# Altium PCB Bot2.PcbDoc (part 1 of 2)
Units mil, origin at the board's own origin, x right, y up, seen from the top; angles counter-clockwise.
Board outline 1717.4 x 2323.5 mil, 2 copper layers (Top1, Bottom2), stack 14.611 mil thick; 246 components, 15 nets, 1108 pads, 443 vias.
Unrouted connection lines stored in the file: 11.
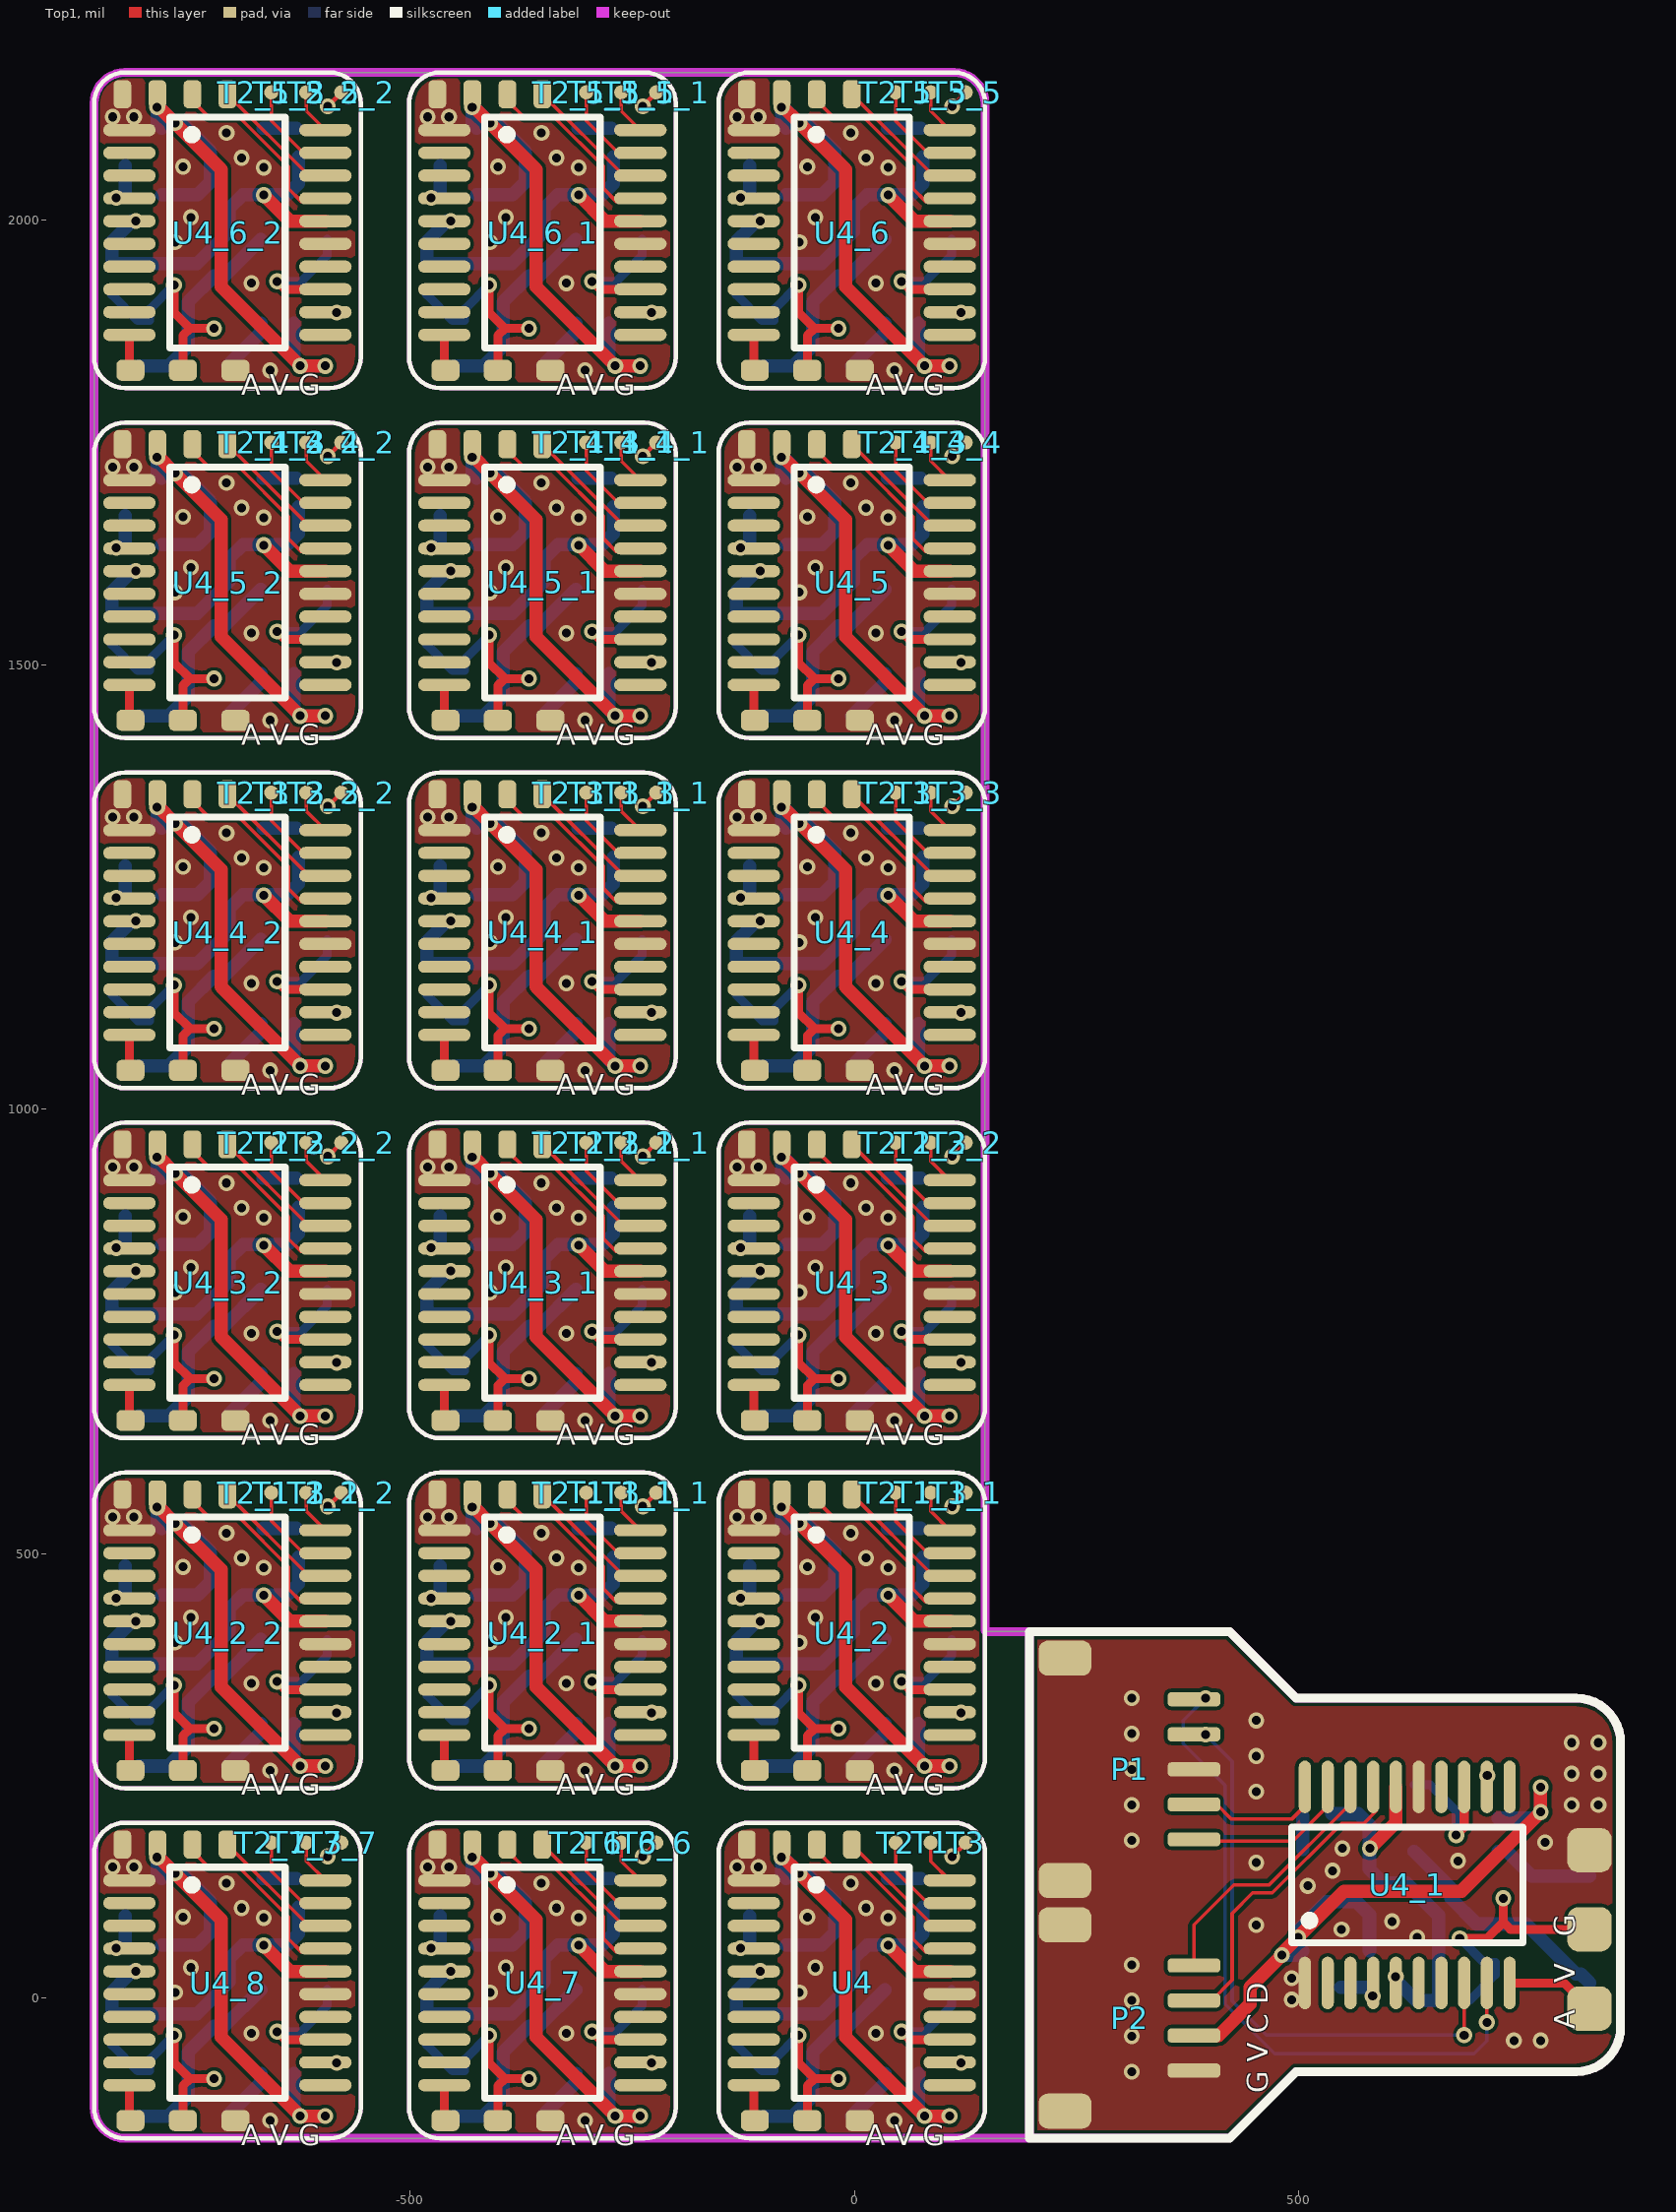
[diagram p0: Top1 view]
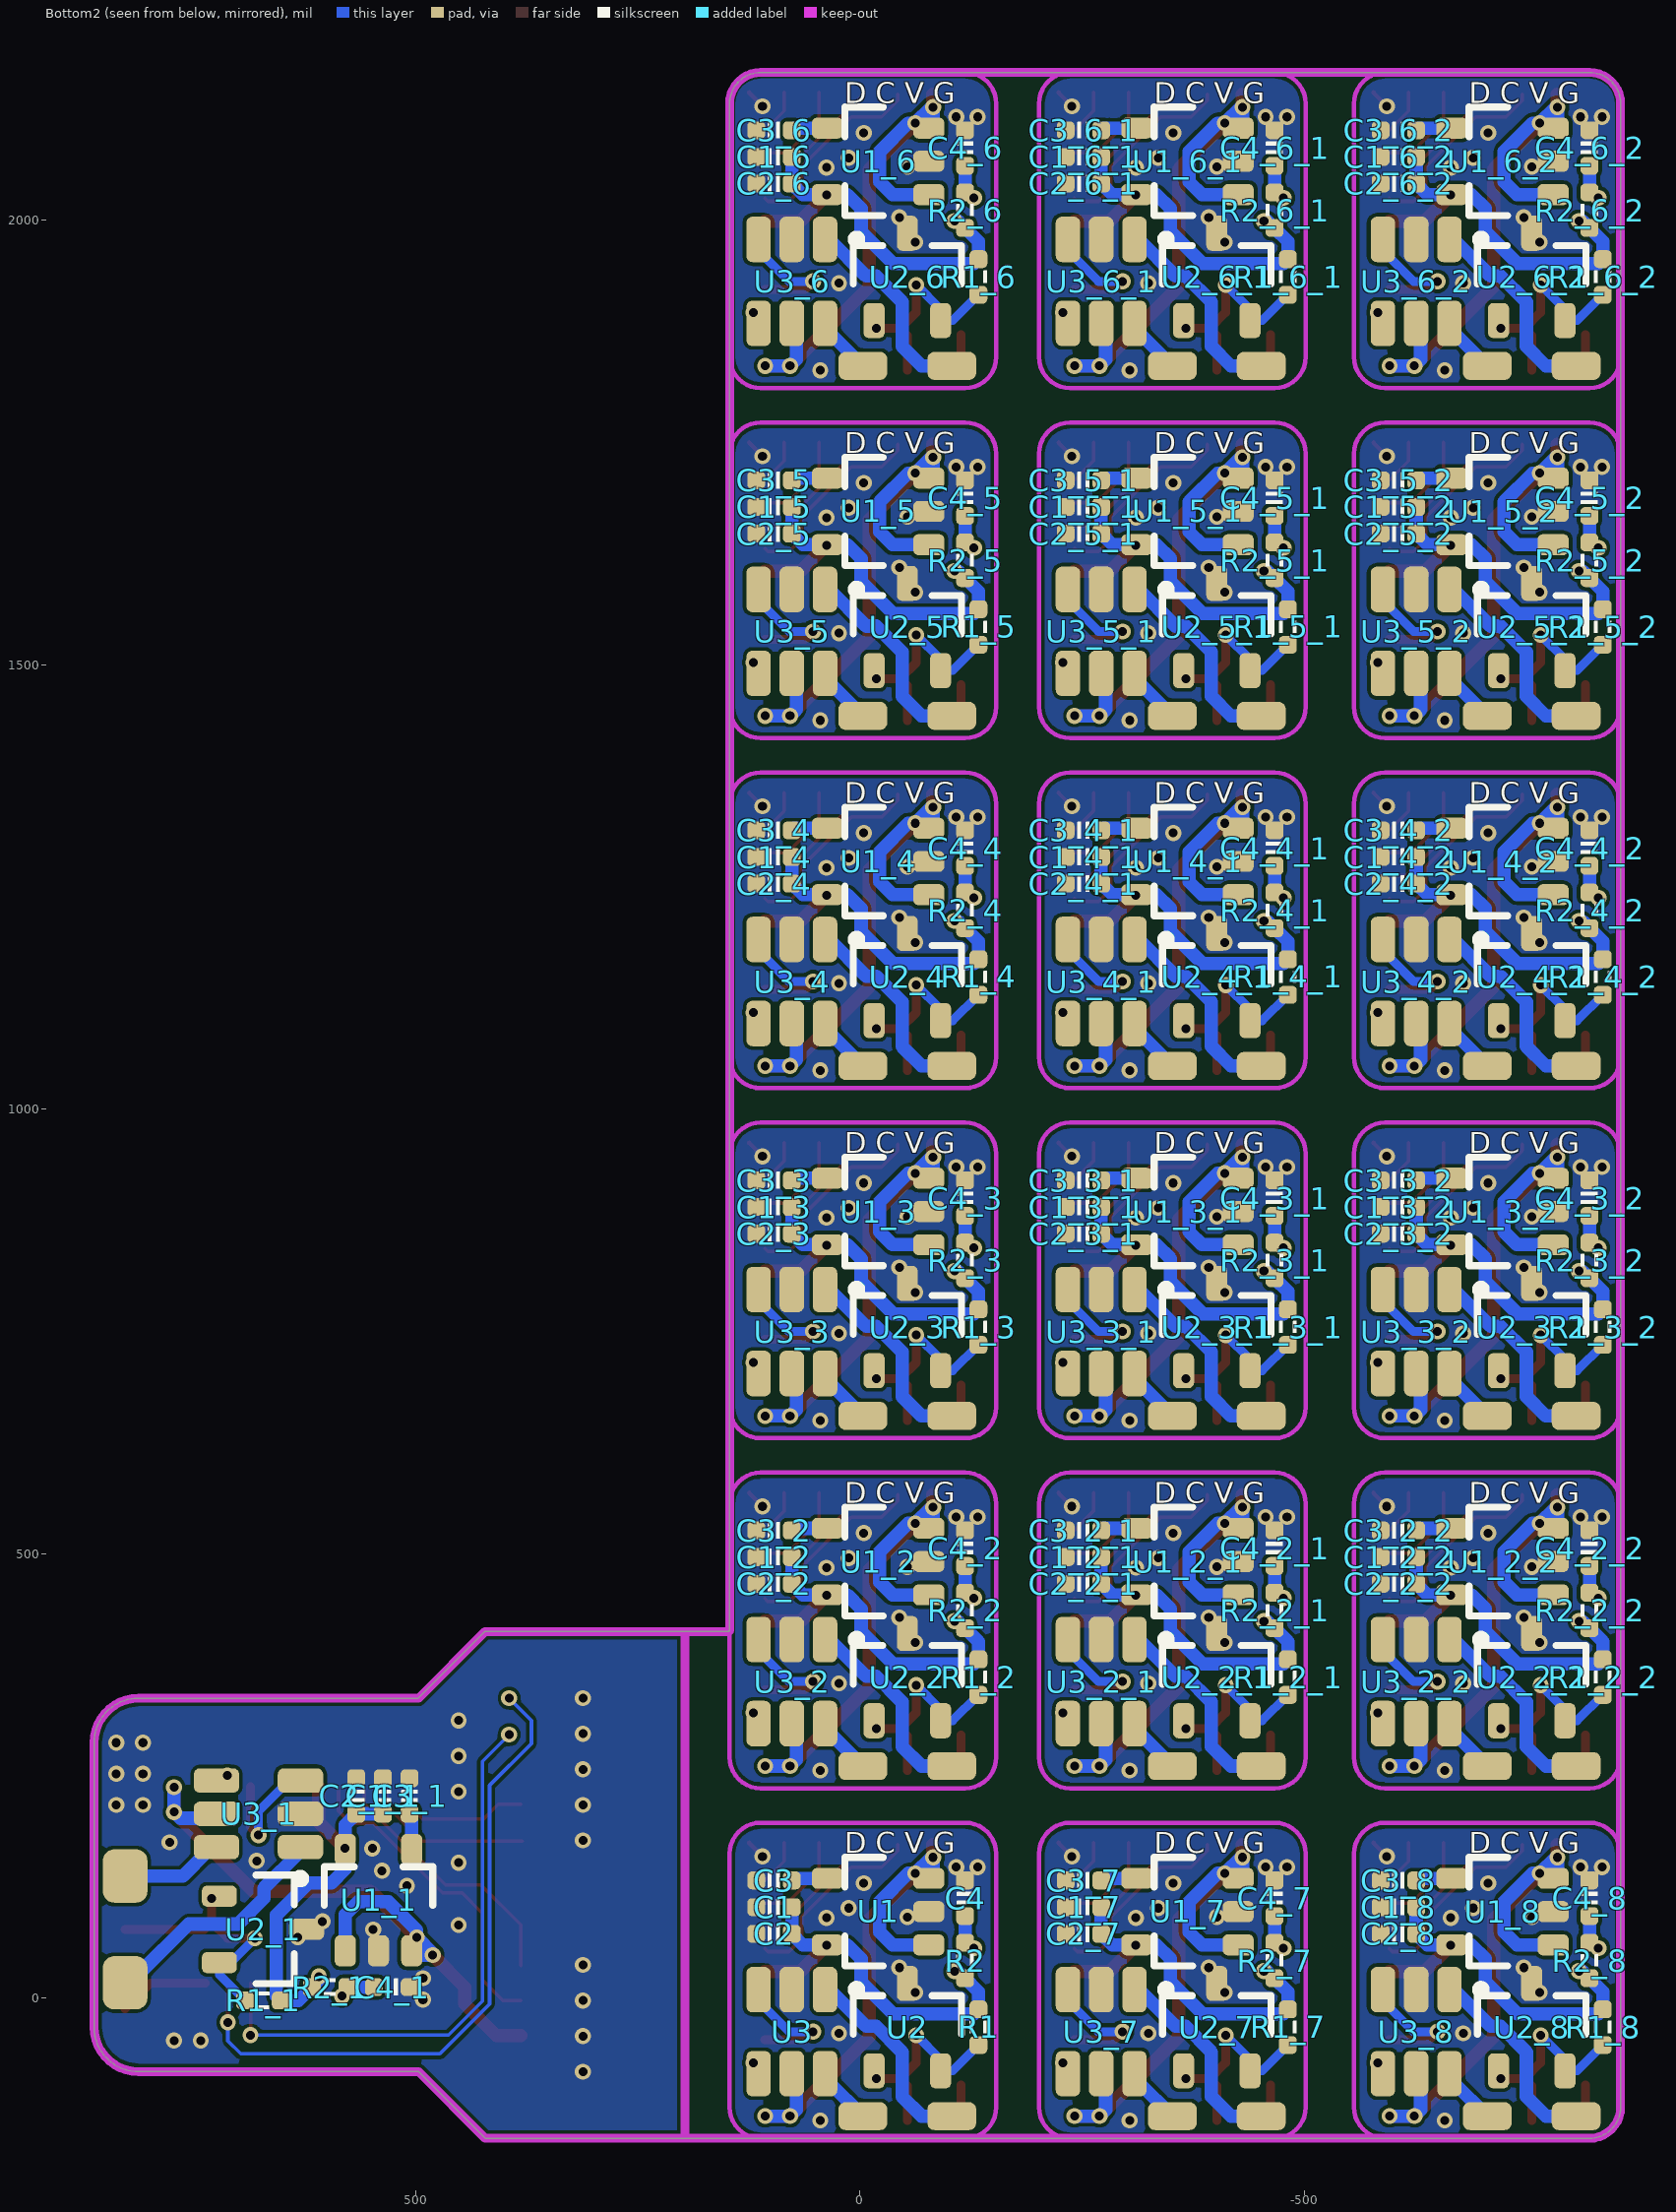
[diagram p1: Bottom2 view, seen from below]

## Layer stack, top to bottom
Top Solder: solder mask 0.4, Solder Resist, Dk 3.5
Top1: signal copper 1.4
Dielectric 1: prepreg 11.811, PP-006, Dk 4.1
Bottom2: signal copper 1.4
Bottom Solder: solder mask 0.4, Solder Resist, Dk 3.5

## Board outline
-855.55,-122.48 ccw(c-820.55,-122.48) -820.55,-157.48 421.85,-157.48 496.85,-82.48 811.85,-82.48 ccw(c811.85,-32.48) 861.85,-32.48 861.85,287.52 ccw(c811.85,287.52) 811.85,337.52 496.85,337.52 421.85,412.52 148.09,412.52 146.89,413.72 146.89,2131.02 ccw(c111.89,2131.02) 111.89,2166.02 -820.55,2166.02 ccw(c-820.55,2131.02) -855.55,2131.02

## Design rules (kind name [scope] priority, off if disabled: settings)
Clearance Clearance_Logo [InNetClass('Logo')] p1: gap=8 ignorepadtopadclearanceinfootprint=FALSE
Clearance [All] p2: gap=4 ignorepadtopadclearanceinfootprint=FALSE except(0: Arc-Hole Track-Hole SMDPad-Hole THPad-Hole Via-Hole Fill-Hole Poly-Hole Region-Hole Text-Hole)
ComponentClearance [All] p1: gap=0 collisioncheckmode=3 verticalgap=0 showdistances=FALSE
DiffPairsRouting [All] p1: maxlimit=9 minlimit=9 mostfreqgap=9 toplayer_minwidth=15 toplayer_maxwidth=15 toplayer_prefwidth=15 bottomlayer_minwidth=15 bottomlayer_maxwidth=15 bottomlayer_prefwidth=15 maxuncoupledlength=500
FanoutControl Fanout_BGA [All] p1: bgadir=Out bgaviamode=Centered fanoutstyle=Auto fanoutdirection=Alternating viagrid=1 // Fanout_BGA (Default Rule)
HoleSize [All] p1: absolutevalues=TRUE maxlimit=10000 minlimit=8 maxpercent=80.000 minpercent=20.000
MinimumSolderMaskSliver [All] p1 off: minsoldermaskwidth=2
PlaneClearance [All] p1: clearance=8
PlaneConnect [All] p1: planeconnectstyle=Direct reliefexpansion=20 reliefentries=4 reliefconductorwidth=10 reliefairgap=10
PolygonConnect [All] p1: connectstyle=Direct reliefconductorwidth=10 reliefentries=4 polygonreliefangle="90 Angle" airgapwidth=10
RoutingVias [All] p1: holewidth=8 width=16 viastyle="Through Hole" minholewidth=6 minwidth=12 maxholewidth=28 maxwidth=50
SilkToSilkClearance [All] p1: silktosilkclearance=0
SilkToSolderMaskClearance [IsPad] p1: minsilkscreentomaskgap=0 clearancetoexposedcopper=TRUE
SolderMaskExpansion [All] p1: expansion=3 istentingtop=FALSE
Width Logo [InNetClass('Logo')] p1: maxlimit=100 minlimit=0.1 preferedwidth=10
Width GND [(InNet('AGND') OR InNet('GND'))] p2: maxlimit=50 minlimit=4 preferedwidth=10
Width VCC [(InNet('VDD_SYS_3.3V') OR InNet('VDD_AV_3.3V') OR InNet('VDD_5V') OR InNet('VDD1V2-SYS') OR InNet('VDD1V1-EPHY') OR InNet('VDD-CPUX') OR InNet('VDD-CPUS') OR InNet('VDD-CPUFB') OR InNet('VCC-DRAM'))] p3: maxlimit=50 minlimit=4 preferedwidth=10
Width [All] p4: maxlimit=10000 minlimit=4 preferedwidth=4
21 further rules are at their usual default settings.

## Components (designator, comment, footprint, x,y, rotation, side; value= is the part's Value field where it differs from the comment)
C1 "10uF" CAP_0402 96.89,102.52 r180 bottom value=0.1u
C1_1 "10uF" CAP_0402 536.85,227.52 r270 bottom value=0.1u (schematic designator C1)
C1_2 "10uF" CAP_0402 96.89,496.22 r180 bottom value=0.1u (schematic designator C1)
C1_2_1 "10uF" CAP_0402 -251.22,496.22 r180 bottom value=0.1u (schematic designator C1)
C1_2_2 "10uF" CAP_0402 -605.55,496.22 r180 bottom value=0.1u (schematic designator C1)
C1_3 "10uF" CAP_0402 96.89,889.92 r180 bottom value=0.1u (schematic designator C1)
C1_3_1 "10uF" CAP_0402 -251.22,889.92 r180 bottom value=0.1u (schematic designator C1)
C1_3_2 "10uF" CAP_0402 -605.55,889.92 r180 bottom value=0.1u (schematic designator C1)
C1_4 "10uF" CAP_0402 96.89,1283.62 r180 bottom value=0.1u (schematic designator C1)
C1_4_1 "10uF" CAP_0402 -251.22,1283.62 r180 bottom value=0.1u (schematic designator C1)
C1_4_2 "10uF" CAP_0402 -605.55,1283.62 r180 bottom value=0.1u (schematic designator C1)
C1_5 "10uF" CAP_0402 96.89,1677.32 r180 bottom value=0.1u (schematic designator C1)
C1_5_1 "10uF" CAP_0402 -251.22,1677.32 r180 bottom value=0.1u (schematic designator C1)
C1_5_2 "10uF" CAP_0402 -605.55,1677.32 r180 bottom value=0.1u (schematic designator C1)
C1_6 "10uF" CAP_0402 96.89,2071.02 r180 bottom value=0.1u (schematic designator C1)
C1_6_1 "10uF" CAP_0402 -251.22,2071.02 r180 bottom value=0.1u (schematic designator C1)
C1_6_2 "10uF" CAP_0402 -605.55,2071.02 r180 bottom value=0.1u (schematic designator C1)
C1_7 "10uF" CAP_0402 -251.22,102.52 r180 bottom value=0.1u (schematic designator C1)
C1_8 "10uF" CAP_0402 -605.55,102.52 r180 bottom value=0.1u (schematic designator C1)
C2 "0.1uF" CAP_0402 96.89,72.52 r180 bottom value=0.1u
C2_1 "0.1uF" CAP_0402 566.85,227.52 r270 bottom value=0.1u (schematic designator C2)
C2_2 "0.1uF" CAP_0402 96.89,466.22 r180 bottom value=0.1u (schematic designator C2)
C2_2_1 "0.1uF" CAP_0402 -251.22,466.22 r180 bottom value=0.1u (schematic designator C2)
C2_2_2 "0.1uF" CAP_0402 -605.55,466.22 r180 bottom value=0.1u (schematic designator C2)
C2_3 "0.1uF" CAP_0402 96.89,859.92 r180 bottom value=0.1u (schematic designator C2)
C2_3_1 "0.1uF" CAP_0402 -251.22,859.92 r180 bottom value=0.1u (schematic designator C2)
C2_3_2 "0.1uF" CAP_0402 -605.55,859.92 r180 bottom value=0.1u (schematic designator C2)
C2_4 "0.1uF" CAP_0402 96.89,1253.62 r180 bottom value=0.1u (schematic designator C2)
C2_4_1 "0.1uF" CAP_0402 -251.22,1253.62 r180 bottom value=0.1u (schematic designator C2)
C2_4_2 "0.1uF" CAP_0402 -605.55,1253.62 r180 bottom value=0.1u (schematic designator C2)
C2_5 "0.1uF" CAP_0402 96.89,1647.32 r180 bottom value=0.1u (schematic designator C2)
C2_5_1 "0.1uF" CAP_0402 -251.22,1647.32 r180 bottom value=0.1u (schematic designator C2)
C2_5_2 "0.1uF" CAP_0402 -605.55,1647.32 r180 bottom value=0.1u (schematic designator C2)
C2_6 "0.1uF" CAP_0402 96.89,2041.02 r180 bottom value=0.1u (schematic designator C2)
C2_6_1 "0.1uF" CAP_0402 -251.22,2041.02 r180 bottom value=0.1u (schematic designator C2)
C2_6_2 "0.1uF" CAP_0402 -605.55,2041.02 r180 bottom value=0.1u (schematic designator C2)
C2_7 "0.1uF" CAP_0402 -251.22,72.52 r180 bottom value=0.1u (schematic designator C2)
C2_8 "0.1uF" CAP_0402 -605.55,72.52 r180 bottom value=0.1u (schematic designator C2)
C3 "10nF" CAP_0402 96.89,132.52 r0 bottom value=0.1u
C3_1 "10nF" CAP_0402 506.85,227.52 r90 bottom value=0.1u (schematic designator C3)
C3_2 "10nF" CAP_0402 96.89,526.22 r0 bottom value=0.1u (schematic designator C3)
C3_2_1 "10nF" CAP_0402 -251.22,526.22 r0 bottom value=0.1u (schematic designator C3)
C3_2_2 "10nF" CAP_0402 -605.55,526.22 r0 bottom value=0.1u (schematic designator C3)
C3_3 "10nF" CAP_0402 96.89,919.92 r0 bottom value=0.1u (schematic designator C3)
C3_3_1 "10nF" CAP_0402 -251.22,919.92 r0 bottom value=0.1u (schematic designator C3)
C3_3_2 "10nF" CAP_0402 -605.55,919.92 r0 bottom value=0.1u (schematic designator C3)
C3_4 "10nF" CAP_0402 96.89,1313.62 r0 bottom value=0.1u (schematic designator C3)
C3_4_1 "10nF" CAP_0402 -251.22,1313.62 r0 bottom value=0.1u (schematic designator C3)
C3_4_2 "10nF" CAP_0402 -605.55,1313.62 r0 bottom value=0.1u (schematic designator C3)
C3_5 "10nF" CAP_0402 96.89,1707.32 r0 bottom value=0.1u (schematic designator C3)
C3_5_1 "10nF" CAP_0402 -251.22,1707.32 r0 bottom value=0.1u (schematic designator C3)
C3_5_2 "10nF" CAP_0402 -605.55,1707.32 r0 bottom value=0.1u (schematic designator C3)
C3_6 "10nF" CAP_0402 96.89,2101.02 r0 bottom value=0.1u (schematic designator C3)
C3_6_1 "10nF" CAP_0402 -251.22,2101.02 r0 bottom value=0.1u (schematic designator C3)
C3_6_2 "10nF" CAP_0402 -605.55,2101.02 r0 bottom value=0.1u (schematic designator C3)
C3_7 "10nF" CAP_0402 -251.22,132.52 r0 bottom value=0.1u (schematic designator C3)
C3_8 "10nF" CAP_0402 -605.55,132.52 r0 bottom value=0.1u (schematic designator C3)
C4 "0.1uF" CAP_0402 -118.11,112.52 r270 bottom value=0.1u
C4_1 "0.1uF" CAP_0402 526.85,12.52 r0 bottom value=0.1u (schematic designator C4)
C4_2 "0.1uF" CAP_0402 -118.11,506.22 r270 bottom value=0.1u (schematic designator C4)
C4_2_1 "0.1uF" CAP_0402 -466.22,506.22 r270 bottom value=0.1u (schematic designator C4)
C4_2_2 "0.1uF" CAP_0402 -820.55,506.22 r270 bottom value=0.1u (schematic designator C4)
C4_3 "0.1uF" CAP_0402 -118.11,899.92 r270 bottom value=0.1u (schematic designator C4)
C4_3_1 "0.1uF" CAP_0402 -466.22,899.92 r270 bottom value=0.1u (schematic designator C4)
C4_3_2 "0.1uF" CAP_0402 -820.55,899.92 r270 bottom value=0.1u (schematic designator C4)
C4_4 "0.1uF" CAP_0402 -118.11,1293.62 r270 bottom value=0.1u (schematic designator C4)
C4_4_1 "0.1uF" CAP_0402 -466.22,1293.62 r270 bottom value=0.1u (schematic designator C4)
C4_4_2 "0.1uF" CAP_0402 -820.55,1293.62 r270 bottom value=0.1u (schematic designator C4)
C4_5 "0.1uF" CAP_0402 -118.11,1687.32 r270 bottom value=0.1u (schematic designator C4)
C4_5_1 "0.1uF" CAP_0402 -466.22,1687.32 r270 bottom value=0.1u (schematic designator C4)
C4_5_2 "0.1uF" CAP_0402 -820.55,1687.32 r270 bottom value=0.1u (schematic designator C4)
C4_6 "0.1uF" CAP_0402 -118.11,2081.02 r270 bottom value=0.1u (schematic designator C4)
C4_6_1 "0.1uF" CAP_0402 -466.22,2081.02 r270 bottom value=0.1u (schematic designator C4)
C4_6_2 "0.1uF" CAP_0402 -820.55,2081.02 r270 bottom value=0.1u (schematic designator C4)
C4_7 "0.1uF" CAP_0402 -466.22,112.52 r270 bottom value=0.1u (schematic designator C4)
C4_8 "0.1uF" CAP_0402 -820.55,112.52 r270 bottom value=0.1u (schematic designator C4)
P1 "SH1.0-5P" SH1.0-5P 381.85,257.52 r270 top
P2 "SH1.0-4P" SH1.0-4P 381.85,-22.17 r270 top
R1 "120R" RES_0402 -133.11,-32.48 r270 bottom value=22R
R1_1 "120R" RES_0402 671.85,-2.48 r0 bottom value=22R (schematic designator R1)
R1_2 "120R" RES_0402 -133.11,361.22 r270 bottom value=22R (schematic designator R1)
R1_2_1 "120R" RES_0402 -481.22,361.22 r270 bottom value=22R (schematic designator R1)
R1_2_2 "120R" RES_0402 -835.55,361.22 r270 bottom value=22R (schematic designator R1)
R1_3 "120R" RES_0402 -133.11,754.92 r270 bottom value=22R (schematic designator R1)
R1_3_1 "120R" RES_0402 -481.22,754.92 r270 bottom value=22R (schematic designator R1)
R1_3_2 "120R" RES_0402 -835.55,754.92 r270 bottom value=22R (schematic designator R1)
R1_4 "120R" RES_0402 -133.11,1148.62 r270 bottom value=22R (schematic designator R1)
R1_4_1 "120R" RES_0402 -481.22,1148.62 r270 bottom value=22R (schematic designator R1)
R1_4_2 "120R" RES_0402 -835.55,1148.62 r270 bottom value=22R (schematic designator R1)
R1_5 "120R" RES_0402 -133.11,1542.32 r270 bottom value=22R (schematic designator R1)
R1_5_1 "120R" RES_0402 -481.22,1542.32 r270 bottom value=22R (schematic designator R1)
R1_5_2 "120R" RES_0402 -835.55,1542.32 r270 bottom value=22R (schematic designator R1)
R1_6 "120R" RES_0402 -133.11,1936.02 r270 bottom value=22R (schematic designator R1)
R1_6_1 "120R" RES_0402 -481.22,1936.02 r270 bottom value=22R (schematic designator R1)
R1_6_2 "120R" RES_0402 -835.55,1936.02 r270 bottom value=22R (schematic designator R1)
R1_7 "120R" RES_0402 -481.22,-32.48 r270 bottom value=22R (schematic designator R1)
R1_8 "120R" RES_0402 -835.55,-32.48 r270 bottom value=22R (schematic designator R1)
R2 "10K" RES_0402 -118.11,42.52 r90 bottom value=22R
R2_1 "10K" RES_0402 596.85,12.52 r180 bottom value=22R (schematic designator R2)
R2_2 "10K" RES_0402 -118.11,436.22 r90 bottom value=22R (schematic designator R2)
R2_2_1 "10K" RES_0402 -466.22,436.22 r90 bottom value=22R (schematic designator R2)
R2_2_2 "10K" RES_0402 -820.55,436.22 r90 bottom value=22R (schematic designator R2)
R2_3 "10K" RES_0402 -118.11,829.92 r90 bottom value=22R (schematic designator R2)
R2_3_1 "10K" RES_0402 -466.22,829.92 r90 bottom value=22R (schematic designator R2)
R2_3_2 "10K" RES_0402 -820.55,829.92 r90 bottom value=22R (schematic designator R2)
R2_4 "10K" RES_0402 -118.11,1223.62 r90 bottom value=22R (schematic designator R2)
R2_4_1 "10K" RES_0402 -466.22,1223.62 r90 bottom value=22R (schematic designator R2)
R2_4_2 "10K" RES_0402 -820.55,1223.62 r90 bottom value=22R (schematic designator R2)
R2_5 "10K" RES_0402 -118.11,1617.32 r90 bottom value=22R (schematic designator R2)
R2_5_1 "10K" RES_0402 -466.22,1617.32 r90 bottom value=22R (schematic designator R2)
R2_5_2 "10K" RES_0402 -820.55,1617.32 r90 bottom value=22R (schematic designator R2)
R2_6 "10K" RES_0402 -118.11,2011.02 r90 bottom value=22R (schematic designator R2)
R2_6_1 "10K" RES_0402 -466.22,2011.02 r90 bottom value=22R (schematic designator R2)
R2_6_2 "10K" RES_0402 -820.55,2011.02 r90 bottom value=22R (schematic designator R2)
R2_7 "10K" RES_0402 -466.22,42.52 r90 bottom value=22R (schematic designator R2)
R2_8 "10K" RES_0402 -820.55,42.52 r90 bottom value=22R (schematic designator R2)
T1 "测试点" TEST_PT 85.63,175 r0 top
T1_1 "测试点" TEST_PT 85.63,568.7 r0 top (schematic designator T1)
T1_1_1 "测试点" TEST_PT -262.48,568.7 r0 top (schematic designator T1)
T1_1_2 "测试点" TEST_PT -616.81,568.7 r0 top (schematic designator T1)
T1_2 "测试点" TEST_PT 85.63,962.4 r0 top (schematic designator T1)
T1_2_1 "测试点" TEST_PT -262.48,962.4 r0 top (schematic designator T1)
T1_2_2 "测试点" TEST_PT -616.81,962.4 r0 top (schematic designator T1)
T1_3 "测试点" TEST_PT 85.63,1356.1 r0 top (schematic designator T1)
T1_3_1 "测试点" TEST_PT -262.48,1356.1 r0 top (schematic designator T1)
T1_3_2 "测试点" TEST_PT -616.81,1356.1 r0 top (schematic designator T1)
T1_4 "测试点" TEST_PT 85.63,1749.8 r0 top (schematic designator T1)
T1_4_1 "测试点" TEST_PT -262.48,1749.8 r0 top (schematic designator T1)
T1_4_2 "测试点" TEST_PT -616.81,1749.8 r0 top (schematic designator T1)
T1_5 "测试点" TEST_PT 85.63,2143.5 r0 top (schematic designator T1)
T1_5_1 "测试点" TEST_PT -262.48,2143.5 r0 top (schematic designator T1)
T1_5_2 "测试点" TEST_PT -616.81,2143.5 r0 top (schematic designator T1)
T1_6 "测试点" TEST_PT -262.48,175 r0 top (schematic designator T1)
T1_7 "测试点" TEST_PT -616.81,175 r0 top (schematic designator T1)
T2 "测试点" TEST_PT 46.26,175 r0 top
T2_1 "测试点" TEST_PT 46.26,568.7 r0 top (schematic designator T2)
T2_1_1 "测试点" TEST_PT -301.85,568.7 r0 top (schematic designator T2)
T2_1_2 "测试点" TEST_PT -656.18,568.7 r0 top (schematic designator T2)
T2_2 "测试点" TEST_PT 46.26,962.4 r0 top (schematic designator T2)
T2_2_1 "测试点" TEST_PT -301.85,962.4 r0 top (schematic designator T2)
T2_2_2 "测试点" TEST_PT -656.18,962.4 r0 top (schematic designator T2)
T2_3 "测试点" TEST_PT 46.26,1356.1 r0 top (schematic designator T2)
T2_3_1 "测试点" TEST_PT -301.85,1356.1 r0 top (schematic designator T2)
T2_3_2 "测试点" TEST_PT -656.18,1356.1 r0 top (schematic designator T2)
T2_4 "测试点" TEST_PT 46.26,1749.8 r0 top (schematic designator T2)
T2_4_1 "测试点" TEST_PT -301.85,1749.8 r0 top (schematic designator T2)
T2_4_2 "测试点" TEST_PT -656.18,1749.8 r0 top (schematic designator T2)
T2_5 "测试点" TEST_PT 46.26,2143.5 r0 top (schematic designator T2)
T2_5_1 "测试点" TEST_PT -301.85,2143.5 r0 top (schematic designator T2)
T2_5_2 "测试点" TEST_PT -656.18,2143.5 r0 top (schematic designator T2)
T2_6 "测试点" TEST_PT -301.85,175 r0 top (schematic designator T2)
T2_7 "测试点" TEST_PT -656.18,175 r0 top (schematic designator T2)
T3 "测试点" TEST_PT 125,175 r0 top
T3_1 "测试点" TEST_PT 125,568.7 r0 top (schematic designator T3)
T3_1_1 "测试点" TEST_PT -223.11,568.7 r0 top (schematic designator T3)
T3_1_2 "测试点" TEST_PT -577.44,568.7 r0 top (schematic designator T3)
T3_2 "测试点" TEST_PT 125,962.4 r0 top (schematic designator T3)
T3_2_1 "测试点" TEST_PT -223.11,962.4 r0 top (schematic designator T3)
T3_2_2 "测试点" TEST_PT -577.44,962.4 r0 top (schematic designator T3)
T3_3 "测试点" TEST_PT 125,1356.1 r0 top (schematic designator T3)
T3_3_1 "测试点" TEST_PT -223.11,1356.1 r0 top (schematic designator T3)
T3_3_2 "测试点" TEST_PT -577.44,1356.1 r0 top (schematic designator T3)
T3_4 "测试点" TEST_PT 125,1749.8 r0 top (schematic designator T3)
T3_4_1 "测试点" TEST_PT -223.11,1749.8 r0 top (schematic designator T3)
T3_4_2 "测试点" TEST_PT -577.44,1749.8 r0 top (schematic designator T3)
T3_5 "测试点" TEST_PT 125,2143.5 r0 top (schematic designator T3)
T3_5_1 "测试点" TEST_PT -223.11,2143.5 r0 top (schematic designator T3)
T3_5_2 "测试点" TEST_PT -577.44,2143.5 r0 top (schematic designator T3)
T3_6 "测试点" TEST_PT -223.11,175 r0 top (schematic designator T3)
T3_7 "测试点" TEST_PT -577.44,175 r0 top (schematic designator T3)
U1 "LP2992" SOT23-5 -18.11,97.52 r0 bottom locked
U1_1 "LP2992" SOT23-5 541.85,112.52 r90 bottom locked (schematic designator U1)
U1_2 "LP2992" SOT23-5 -18.11,491.22 r0 bottom locked (schematic designator U1)
U1_2_1 "LP2992" SOT23-5 -366.22,491.22 r0 bottom locked (schematic designator U1)
U1_2_2 "LP2992" SOT23-5 -720.55,491.22 r0 bottom locked (schematic designator U1)
U1_3 "LP2992" SOT23-5 -18.11,884.92 r0 bottom locked (schematic designator U1)
U1_3_1 "LP2992" SOT23-5 -366.22,884.92 r0 bottom locked (schematic designator U1)
U1_3_2 "LP2992" SOT23-5 -720.55,884.92 r0 bottom locked (schematic designator U1)
U1_4 "LP2992" SOT23-5 -18.11,1278.62 r0 bottom locked (schematic designator U1)
U1_4_1 "LP2992" SOT23-5 -366.22,1278.62 r0 bottom locked (schematic designator U1)
U1_4_2 "LP2992" SOT23-5 -720.55,1278.62 r0 bottom locked (schematic designator U1)
U1_5 "LP2992" SOT23-5 -18.11,1672.32 r0 bottom locked (schematic designator U1)
U1_5_1 "LP2992" SOT23-5 -366.22,1672.32 r0 bottom locked (schematic designator U1)
U1_5_2 "LP2992" SOT23-5 -720.55,1672.32 r0 bottom locked (schematic designator U1)
U1_6 "LP2992" SOT23-5 -18.11,2066.02 r0 bottom locked (schematic designator U1)
U1_6_1 "LP2992" SOT23-5 -366.22,2066.02 r0 bottom locked (schematic designator U1)
U1_6_2 "LP2992" SOT23-5 -720.55,2066.02 r0 bottom locked (schematic designator U1)
U1_7 "LP2992" SOT23-5 -366.22,97.52 r0 bottom locked (schematic designator U1)
U1_8 "LP2992" SOT23-5 -720.55,97.52 r0 bottom locked (schematic designator U1)
U2 "TL431IDBZT" SOT23-3 -53.11,-32.48 r90 bottom
U2_1 "TL431IDBZT" SOT23-3 671.85,77.52 r180 bottom (schematic designator U2)
U2_2 "TL431IDBZT" SOT23-3 -53.11,361.22 r90 bottom (schematic designator U2)
U2_2_1 "TL431IDBZT" SOT23-3 -401.22,361.22 r90 bottom (schematic designator U2)
U2_2_2 "TL431IDBZT" SOT23-3 -755.55,361.22 r90 bottom (schematic designator U2)
U2_3 "TL431IDBZT" SOT23-3 -53.11,754.92 r90 bottom (schematic designator U2)
U2_3_1 "TL431IDBZT" SOT23-3 -401.22,754.92 r90 bottom (schematic designator U2)
U2_3_2 "TL431IDBZT" SOT23-3 -755.55,754.92 r90 bottom (schematic designator U2)
U2_4 "TL431IDBZT" SOT23-3 -53.11,1148.62 r90 bottom (schematic designator U2)
U2_4_1 "TL431IDBZT" SOT23-3 -401.22,1148.62 r90 bottom (schematic designator U2)
U2_4_2 "TL431IDBZT" SOT23-3 -755.55,1148.62 r90 bottom (schematic designator U2)
U2_5 "TL431IDBZT" SOT23-3 -53.11,1542.32 r90 bottom (schematic designator U2)
U2_5_1 "TL431IDBZT" SOT23-3 -401.22,1542.32 r90 bottom (schematic designator U2)
U2_5_2 "TL431IDBZT" SOT23-3 -755.55,1542.32 r90 bottom (schematic designator U2)
U2_6 "TL431IDBZT" SOT23-3 -53.11,1936.02 r90 bottom (schematic designator U2)
U2_6_1 "TL431IDBZT" SOT23-3 -401.22,1936.02 r90 bottom (schematic designator U2)
U2_6_2 "TL431IDBZT" SOT23-3 -755.55,1936.02 r90 bottom (schematic designator U2)
U2_7 "TL431IDBZT" SOT23-3 -401.22,-32.48 r90 bottom (schematic designator U2)
U2_8 "TL431IDBZT" SOT23-3 -755.55,-32.48 r90 bottom (schematic designator U2)
U3 "FM116B" SOT23-6 76.89,-37.48 r270 bottom
U3_1 "FM116B" SOT23-6 676.85,207.52 r0 bottom (schematic designator U3)
U3_2 "FM116B" SOT23-6 76.89,356.22 r270 bottom (schematic designator U3)
U3_2_1 "FM116B" SOT23-6 -271.22,356.22 r270 bottom (schematic designator U3)
U3_2_2 "FM116B" SOT23-6 -625.55,356.22 r270 bottom (schematic designator U3)
U3_3 "FM116B" SOT23-6 76.89,749.92 r270 bottom (schematic designator U3)
U3_3_1 "FM116B" SOT23-6 -271.22,749.92 r270 bottom (schematic designator U3)
U3_3_2 "FM116B" SOT23-6 -625.55,749.92 r270 bottom (schematic designator U3)
U3_4 "FM116B" SOT23-6 76.89,1143.62 r270 bottom (schematic designator U3)
U3_4_1 "FM116B" SOT23-6 -271.22,1143.62 r270 bottom (schematic designator U3)
U3_4_2 "FM116B" SOT23-6 -625.55,1143.62 r270 bottom (schematic designator U3)
U3_5 "FM116B" SOT23-6 76.89,1537.32 r270 bottom (schematic designator U3)
U3_5_1 "FM116B" SOT23-6 -271.22,1537.32 r270 bottom (schematic designator U3)
U3_5_2 "FM116B" SOT23-6 -625.55,1537.32 r270 bottom (schematic designator U3)
U3_6 "FM116B" SOT23-6 76.89,1931.02 r270 bottom (schematic designator U3)
U3_6_1 "FM116B" SOT23-6 -271.22,1931.02 r270 bottom (schematic designator U3)
U3_6_2 "FM116B" SOT23-6 -625.55,1931.02 r270 bottom (schematic designator U3)
U3_7 "FM116B" SOT23-6 -271.22,-37.48 r270 bottom (schematic designator U3)
U3_8 "FM116B" SOT23-6 -625.55,-37.48 r270 bottom (schematic designator U3)
U4 "STM32F030F6/STM32F042F6" TSSOP-20 -3.11,17.52 r0 top locked
U4_1 "STM32F030F6/STM32F042F6" TSSOP-20 621.85,127.52 r90 top locked (schematic designator U4)
U4_2 "STM32F030F6/STM32F042F6" TSSOP-20 -3.11,411.22 r0 top locked (schematic designator U4)
U4_2_1 "STM32F030F6/STM32F042F6" TSSOP-20 -351.22,411.22 r0 top locked (schematic designator U4)
U4_2_2 "STM32F030F6/STM32F042F6" TSSOP-20 -705.55,411.22 r0 top locked (schematic designator U4)
U4_3 "STM32F030F6/STM32F042F6" TSSOP-20 -3.11,804.92 r0 top locked (schematic designator U4)
U4_3_1 "STM32F030F6/STM32F042F6" TSSOP-20 -351.22,804.92 r0 top locked (schematic designator U4)
U4_3_2 "STM32F030F6/STM32F042F6" TSSOP-20 -705.55,804.92 r0 top locked (schematic designator U4)
U4_4 "STM32F030F6/STM32F042F6" TSSOP-20 -3.11,1198.62 r0 top locked (schematic designator U4)
U4_4_1 "STM32F030F6/STM32F042F6" TSSOP-20 -351.22,1198.62 r0 top locked (schematic designator U4)
U4_4_2 "STM32F030F6/STM32F042F6" TSSOP-20 -705.55,1198.62 r0 top locked (schematic designator U4)
U4_5 "STM32F030F6/STM32F042F6" TSSOP-20 -3.11,1592.32 r0 top locked (schematic designator U4)
U4_5_1 "STM32F030F6/STM32F042F6" TSSOP-20 -351.22,1592.32 r0 top locked (schematic designator U4)
U4_5_2 "STM32F030F6/STM32F042F6" TSSOP-20 -705.55,1592.32 r0 top locked (schematic designator U4)
U4_6 "STM32F030F6/STM32F042F6" TSSOP-20 -3.11,1986.02 r0 top locked (schematic designator U4)
U4_6_1 "STM32F030F6/STM32F042F6" TSSOP-20 -351.22,1986.02 r0 top locked (schematic designator U4)
U4_6_2 "STM32F030F6/STM32F042F6" TSSOP-20 -705.55,1986.02 r0 top locked (schematic designator U4)
U4_7 "STM32F030F6/STM32F042F6" TSSOP-20 -351.22,17.52 r0 top locked (schematic designator U4)
U4_8 "STM32F030F6/STM32F042F6" TSSOP-20 -705.55,17.52 r0 top locked (schematic designator U4)

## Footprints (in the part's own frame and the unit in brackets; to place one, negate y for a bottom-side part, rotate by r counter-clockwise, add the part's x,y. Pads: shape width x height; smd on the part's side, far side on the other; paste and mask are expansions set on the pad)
CAP_0402 [mil]
  rrect50% 20x20 smd: 1(-20,0) 2(20,0)
  silkscreen extent -7,-9 7,9, body extent -20,-10 20,10, height 20
RES_0402 [mil]
  rrect50% 20x20 smd: 1(-20,0) 2(20,0)
  silkscreen extent -7,-10 7,10, body extent -20,-10 20,10, height 14
SH1.0-4P [mm]
  rrect50% 0.4x1.5 smd: 1(-1.5,0) 2(-0.5,0) 3(0.5,0) 4(1.5,0)
  rrect50% 1x1.5 smd: SH1(-2.659,-3.683) SH2(2.659,-3.683)
  body extent -3,-4.42 3,0.54, height 3.14
SH1.0-5P [mm]
  rrect50% 0.4x1.5 smd: 1(-2,0) 2(-1,0) 3(0,0) 4(1,0) 5(2,0)
  rrect50% 1x1.5 smd: SH1(-3.175,-3.683) SH2(3.175,-3.683)
  body extent -3.5,-4.42 3.5,0.54, height 3.06
SOT23-3 [mm] "SOT23, 3-Leads, Body 3.1x3.0mm (max), Pitch 0.95mm, IPC Medium Density"
  rrect50% 1x0.6 smd: 1(-1.246,0.95) 2(-1.246,-0.95) 3(1.246,0)
  silkscreen extent -0.2,-1.55 0.9,1.55, body extent -1.3,-1.45 1.5,1.45, height 1.2
SOT23-5 [mm] "SOT23, 3-Leads, Body 3.1x3.0mm (max), Pitch 0.95mm, IPC Medium Density"
  rrect50% 0.889x0.6 smd: 1(-1.5,0.95) 2(-1.5,0) 3(-1.5,-0.95) 4(1.396,-0.95) 5(1.396,0.95)
  silkscreen extent -0.2,-1.55 0.9,1.55, body extent -1.48,-1.45 1.32,1.45, height 1.2
SOT23-6 [mm]
  rrect50% 1.3x0.7 smd: 1(-1.2,0.95) 2(-1.2,0) 3(-1.2,-0.95) 4(1.2,-0.95) 5(1.2,0) 6(1.2,0.95)
  silkscreen extent -1.32,1.73 -1.08,1.97, body extent -1.4,-1.45 1.4,1.45, height 1.45
TEST_PT [mil]
  rrect100% 16x16 smd: 0(0,0.01)
TSSOP-20 [mm] "SOP, 20-Leads, Body 6.6x4.5mm, Pitch 0.65mm, IPC High Density"
  oval 1.5x0.35 smd: 1(-2.8,2.925) 2(-2.8,2.275) 3(-2.8,1.625) 4(-2.8,0.975) 5(-2.8,0.325) 6(-2.8,-0.325) 7(-2.8,-0.975) 8(-2.8,-1.625) 9(-2.8,-2.275) 10(-2.8,-2.925) 11(2.8,-2.925) 12(2.8,-2.275) 13(2.8,-1.625) 14(2.8,-0.975) 15(2.8,-0.325) 16(2.8,0.325) 17(2.8,0.975) 18(2.8,1.625) 19(2.8,2.275) 20(2.8,2.925)
  silkscreen extent -1.65,-3.3 1.65,3.3, body extent -3.27,-3.3 3.27,3.3, height 1.2

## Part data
C1 C1_1 C1_2 C1_2_1 C1_2_2 C1_3 C1_3_1 C1_3_2 C1_4 C1_4_1 C1_4_2 C1_5 C1_5_1 C1_5_2 C1_6 C1_6_1 C1_6_2 C1_7 C1_8 C2 C2_1 C2_2 C2_2_1 C2_2_2 C2_3 C2_3_1 C2_3_2 C2_4 C2_4_1 C2_4_2 C2_5 C2_5_1 C2_5_2 C2_6 C2_6_1 C2_6_2 C2_7 C2_8 C3 C3_1 C3_2 C3_2_1 C3_2_2 C3_3 C3_3_1 C3_3_2 C3_4 C3_4_1 C3_4_2 C3_5 C3_5_1 C3_5_2 C3_6 C3_6_1 C3_6_2 C3_7 C3_8 C4 C4_1 C4_2 C4_2_1 C4_2_2 C4_3 C4_3_1 C4_3_2 C4_4 C4_4_1 C4_4_2 C4_5 C4_5_1 C4_5_2 C4_6 C4_6_1 C4_6_2 C4_7 C4_8: library part 电容-0402, "Capacitor"
R1 R1_1 R1_2 R1_2_1 R1_2_2 R1_3 R1_3_1 R1_3_2 R1_4 R1_4_1 R1_4_2 R1_5 R1_5_1 R1_5_2 R1_6 R1_6_1 R1_6_2 R1_7 R1_8 R2 R2_1 R2_2 R2_2_1 R2_2_2 R2_3 R2_3_1 R2_3_2 R2_4 R2_4_1 R2_4_2 R2_5 R2_5_1 R2_5_2 R2_6 R2_6_1 R2_6_2 R2_7 R2_8: library part 电阻-0402, "Resistor"
U1 U1_1 U1_2 U1_2_1 U1_2_2 U1_3 U1_3_1 U1_3_2 U1_4 U1_4_1 U1_4_2 U1_5 U1_5_1 U1_5_2 U1_6 U1_6_1 U1_6_2 U1_7 U1_8: "LDO"
U2 U2_1 U2_2 U2_2_1 U2_2_2 U2_3 U2_3_1 U2_3_2 U2_4 U2_4_1 U2_4_2 U2_5 U2_5_1 U2_5_2 U2_6 U2_6_1 U2_6_2 U2_7 U2_8: "Adjustable precision shunt regulator 3-SOT-23 -40 to 85", Package="SOT-23-3 Texas Instruments"
U3 U3_1 U3_2 U3_2_1 U3_2_2 U3_3 U3_3_1 U3_3_2 U3_4 U3_4_1 U3_4_2 U3_5 U3_5_1 U3_5_2 U3_6 U3_6_1 U3_6_2 U3_7 U3_8: PartNumber=24LC256-I/ST
U4 U4_1 U4_2 U4_2_1 U4_2_2 U4_3 U4_3_1 U4_3_2 U4_4 U4_4_1 U4_4_2 U4_5 U4_5_1 U4_5_2 U4_6 U4_6_1 U4_6_2 U4_7 U4_8: library part STM32F030F4P6, "ARM Cortex-M0 32-bit MCU, 16 KB Flash, 4 KB Internal RAM, 15 I/Os, 20-pin TSSOP, -40 to 85 degC, Tube", I/Os (High Current)=15, Operating Frequency(F) (Processor speed) (MHz)=48, Supplier Part Number 1=497-14044-5-ND, Supply Voltage(Vcc) min (V)=2.4

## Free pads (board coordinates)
  rrect50% 19.68x31.5 smd: ""(-823.66,173) ""(-823.66,566.7) ""(-823.66,960.4) ""(-823.66,1354.1) ""(-823.66,1747.8) ""(-823.66,2141.5) ""(-784.29,173) ""(-784.29,566.7) ""(-784.29,960.4) ""(-784.29,1354.1) ""(-784.29,1747.8) ""(-784.29,2141.5) ""(-744.92,173) ""(-744.92,566.7) ""(-744.92,960.4) ""(-744.92,1354.1) ""(-744.92,1747.8) ""(-744.92,2141.5) ""(-705.55,173) ""(-705.55,566.7) ""(-705.55,960.4) ""(-705.55,1354.1) ""(-705.55,1747.8) ""(-705.55,2141.5) ""(-469.33,173) ""(-469.33,566.7) ""(-469.33,960.4) ""(-469.33,1354.1) ""(-469.33,1747.8) ""(-469.33,2141.5) ""(-429.96,173) ""(-429.96,566.7) ""(-429.96,960.4) ""(-429.96,1354.1) ""(-429.96,1747.8) ""(-429.96,2141.5) ""(-390.59,173) ""(-390.59,566.7) ""(-390.59,960.4) ""(-390.59,1354.1) ""(-390.59,1747.8) ""(-390.59,2141.5) ""(-351.22,173) ""(-351.22,566.7) ""(-351.22,960.4) ""(-351.22,1354.1) ""(-351.22,1747.8) ""(-351.22,2141.5) ""(-121.22,173) ""(-121.22,566.7) ""(-121.22,960.4) ""(-121.22,1354.1) ""(-121.22,1747.8) ""(-121.22,2141.5) ""(-81.85,173) ""(-81.85,566.7) ""(-81.85,960.4) ""(-81.85,1354.1) ""(-81.85,1747.8) ""(-81.85,2141.5) ""(-42.48,173) ""(-42.48,566.7) ""(-42.48,960.4) ""(-42.48,1354.1) ""(-42.48,1747.8) ""(-42.48,2141.5) ""(-3.11,173) ""(-3.11,566.7) ""(-3.11,960.4) ""(-3.11,1354.1) ""(-3.11,1747.8) ""(-3.11,2141.5)
  rrect50% 31.5x23.62 smd: ""(-814.61,-137.48) ""(-814.61,256.22) ""(-814.61,649.92) ""(-814.61,1043.62) ""(-814.61,1437.32) ""(-814.61,1831.02) ""(-755.55,-137.48) ""(-755.55,256.22) ""(-755.55,649.92) ""(-755.55,1043.62) ""(-755.55,1437.32) ""(-755.55,1831.02) ""(-696.5,-137.48) ""(-696.5,256.22) ""(-696.5,649.92) ""(-696.5,1043.62) ""(-696.5,1437.32) ""(-696.5,1831.02) ""(-460.28,-137.48) ""(-460.28,256.22) ""(-460.28,649.92) ""(-460.28,1043.62) ""(-460.28,1437.32) ""(-460.28,1831.02) ""(-401.22,-137.48) ""(-401.22,256.22) ""(-401.22,649.92) ""(-401.22,1043.62) ""(-401.22,1437.32) ""(-401.22,1831.02) ""(-342.17,-137.48) ""(-342.17,256.22) ""(-342.17,649.92) ""(-342.17,1043.62) ""(-342.17,1437.32) ""(-342.17,1831.02) ""(-112.17,-137.48) ""(-112.17,256.22) ""(-112.17,649.92) ""(-112.17,1043.62) ""(-112.17,1437.32) ""(-112.17,1831.02) ""(-53.11,-137.48) ""(-53.11,256.22) ""(-53.11,649.92) ""(-53.11,1043.62) ""(-53.11,1437.32) ""(-53.11,1831.02) ""(5.94,-137.48) ""(5.94,256.22) ""(5.94,649.92) ""(5.94,1043.62) ""(5.94,1437.32) ""(5.94,1831.02)
  rrect50% 55x31.5 smd far side: ""(-805.55,-132.48) ""(-805.55,261.22) ""(-805.55,654.92) ""(-805.55,1048.62) ""(-805.55,1442.32) ""(-805.55,1836.02) ""(-705.55,-132.48) ""(-705.55,261.22) ""(-705.55,654.92) ""(-705.55,1048.62) ""(-705.55,1442.32) ""(-705.55,1836.02) ""(-451.22,-132.48) ""(-451.22,261.22) ""(-451.22,654.92) ""(-451.22,1048.62) ""(-451.22,1442.32) ""(-451.22,1836.02) ""(-351.22,-132.48) ""(-351.22,261.22) ""(-351.22,654.92) ""(-351.22,1048.62) ""(-351.22,1442.32) ""(-351.22,1836.02) ""(-103.11,-132.48) ""(-103.11,261.22) ""(-103.11,654.92) ""(-103.11,1048.62) ""(-103.11,1442.32) ""(-103.11,1836.02) ""(-3.11,-132.48) ""(-3.11,261.22) ""(-3.11,654.92) ""(-3.11,1048.62) ""(-3.11,1442.32) ""(-3.11,1836.02)
  rrect50% 50x50 smd: ""(826.85,-11.54) ""(826.85,77.52) ""(826.85,166.57)
  rrect50% 50x60 smd far side: ""(826.85,17.52) ""(826.85,137.52)

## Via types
v1: diameter 18, hole 10, Top1 to Bottom2, tented both sides, 443 vias

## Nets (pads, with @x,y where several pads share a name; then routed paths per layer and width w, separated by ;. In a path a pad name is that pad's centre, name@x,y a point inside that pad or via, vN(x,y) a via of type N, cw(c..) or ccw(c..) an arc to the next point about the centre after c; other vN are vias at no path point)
ADC_1: 
GND: 
NetC3_1: 
NetC4_2: 
OUT1_1: 
OUT2_1: 
PWM1_1: 
PWM2_1: 
SCL_1: 
SDA_1: 
SWCLK_1: 
SWDIO_1: 
VCC_3V3: 
VCC_5V: 
VREF: 
pads on no net: C1.1 C1.2 C1_1.1 C1_1.2 C1_2.1 C1_2.2 C1_2_1.1 C1_2_1.2 C1_2_2.1 C1_2_2.2 C1_3.1 C1_3.2 C1_3_1.1 C1_3_1.2 C1_3_2.1 C1_3_2.2 C1_4.1 C1_4.2 C1_4_1.1 C1_4_1.2 C1_4_2.1 C1_4_2.2 C1_5.1 C1_5.2 C1_5_1.1 C1_5_1.2 C1_5_2.1 C1_5_2.2 C1_6.1 C1_6.2 C1_6_1.1 C1_6_1.2 C1_6_2.1 C1_6_2.2 C1_7.1 C1_7.2 C1_8.1 C1_8.2 C2.1 C2.2 C2_1.1 C2_1.2 C2_2.1 C2_2.2 C2_2_1.1 C2_2_1.2 C2_2_2.1 C2_2_2.2 C2_3.1 C2_3.2 C2_3_1.1 C2_3_1.2 C2_3_2.1 C2_3_2.2 C2_4.1 C2_4.2 C2_4_1.1 C2_4_1.2 C2_4_2.1 C2_4_2.2 C2_5.1 C2_5.2 C2_5_1.1 C2_5_1.2 C2_5_2.1 C2_5_2.2 C2_6.1 C2_6.2 C2_6_1.1 C2_6_1.2 C2_6_2.1 C2_6_2.2 C2_7.1 C2_7.2 C2_8.1 C2_8.2 C3.1 C3.2 C3_1.1 C3_1.2 C3_2.1 C3_2.2 C3_2_1.1 C3_2_1.2 C3_2_2.1 C3_2_2.2 C3_3.1 C3_3.2 C3_3_1.1 C3_3_1.2 C3_3_2.1 C3_3_2.2 C3_4.1 C3_4.2 C3_4_1.1 C3_4_1.2 C3_4_2.1 C3_4_2.2 C3_5.1 C3_5.2 C3_5_1.1 C3_5_1.2 C3_5_2.1 C3_5_2.2 C3_6.1 C3_6.2 C3_6_1.1 C3_6_1.2 C3_6_2.1 C3_6_2.2 C3_7.1 C3_7.2 C3_8.1 C3_8.2 C4.1 C4.2 C4_1.1 C4_1.2 C4_2.1 C4_2.2 C4_2_1.1 C4_2_1.2 C4_2_2.1 C4_2_2.2 C4_3.1 C4_3.2 C4_3_1.1 C4_3_1.2 C4_3_2.1 C4_3_2.2 C4_4.1 C4_4.2 C4_4_1.1 C4_4_1.2 C4_4_2.1 C4_4_2.2 C4_5.1 C4_5.2 C4_5_1.1 C4_5_1.2 C4_5_2.1 C4_5_2.2 C4_6.1 C4_6.2 C4_6_1.1 C4_6_1.2 C4_6_2.1 C4_6_2.2 C4_7.1 C4_7.2 C4_8.1 C4_8.2 P1.1 P1.2 P1.3 P1.4 P1.5 P1.SH1 P1.SH2 P2.1 P2.2 P2.3 P2.4 P2.SH1 P2.SH2 R1.1 R1.2 R1_1.1 R1_1.2 R1_2.1 R1_2.2 R1_2_1.1 R1_2_1.2 R1_2_2.1 R1_2_2.2 R1_3.1 R1_3.2 R1_3_1.1 R1_3_1.2 R1_3_2.1 R1_3_2.2 R1_4.1 R1_4.2 R1_4_1.1 R1_4_1.2 R1_4_2.1 R1_4_2.2 R1_5.1 R1_5.2 R1_5_1.1 R1_5_1.2 R1_5_2.1 R1_5_2.2 R1_6.1 R1_6.2 R1_6_1.1 R1_6_1.2 R1_6_2.1 R1_6_2.2 R1_7.1 R1_7.2 R1_8.1 R1_8.2 R2.1 R2.2 R2_1.1 R2_1.2 R2_2.1 R2_2.2 R2_2_1.1 R2_2_1.2 R2_2_2.1 R2_2_2.2 R2_3.1 R2_3.2 R2_3_1.1 R2_3_1.2 R2_3_2.1 R2_3_2.2 R2_4.1 R2_4.2 R2_4_1.1 R2_4_1.2 R2_4_2.1 R2_4_2.2 R2_5.1 R2_5.2 R2_5_1.1 R2_5_1.2 R2_5_2.1 R2_5_2.2 R2_6.1 R2_6.2 R2_6_1.1 R2_6_1.2 R2_6_2.1 R2_6_2.2 R2_7.1 R2_7.2 R2_8.1 R2_8.2 T1.0 T1_1.0 T1_1_1.0 T1_1_2.0 T1_2.0 T1_2_1.0 T1_2_2.0 T1_3.0 T1_3_1.0 T1_3_2.0 T1_4.0 T1_4_1.0 T1_4_2.0 T1_5.0 T1_5_1.0 T1_5_2.0 T1_6.0 T1_7.0 T2.0 T2_1.0 T2_1_1.0 T2_1_2.0 T2_2.0 T2_2_1.0 T2_2_2.0 T2_3.0 T2_3_1.0 T2_3_2.0 T2_4.0 T2_4_1.0 T2_4_2.0 T2_5.0 T2_5_1.0 T2_5_2.0 T2_6.0 T2_7.0 T3.0 T3_1.0 T3_1_1.0 T3_1_2.0 T3_2.0 T3_2_1.0 T3_2_2.0 T3_3.0 T3_3_1.0 T3_3_2.0 T3_4.0 T3_4_1.0 T3_4_2.0 T3_5.0 T3_5_1.0 T3_5_2.0 T3_6.0 T3_7.0 U1.1 U1.2 U1.3 U1.4 U1.5 U1_1.1 U1_1.2 U1_1.3 U1_1.4 U1_1.5 U1_2.1 U1_2.2 U1_2.3 U1_2.4 U1_2.5 U1_2_1.1 U1_2_1.2 U1_2_1.3 U1_2_1.4 U1_2_1.5 U1_2_2.1 U1_2_2.2 U1_2_2.3 U1_2_2.4 U1_2_2.5 U1_3.1 U1_3.2 U1_3.3 U1_3.4 U1_3.5 U1_3_1.1 U1_3_1.2 U1_3_1.3 U1_3_1.4 U1_3_1.5 U1_3_2.1 U1_3_2.2 U1_3_2.3 U1_3_2.4 U1_3_2.5 U1_4.1 U1_4.2 U1_4.3 U1_4.4 U1_4.5 U1_4_1.1 U1_4_1.2 U1_4_1.3 U1_4_1.4 U1_4_1.5 U1_4_2.1 U1_4_2.2 U1_4_2.3 U1_4_2.4 U1_4_2.5 U1_5.1 U1_5.2 U1_5.3 U1_5.4 U1_5.5 U1_5_1.1 U1_5_1.2 U1_5_1.3 U1_5_1.4 U1_5_1.5 U1_5_2.1 U1_5_2.2 U1_5_2.3 U1_5_2.4 U1_5_2.5 U1_6.1 U1_6.2 U1_6.3 U1_6.4 U1_6.5 U1_6_1.1 U1_6_1.2 U1_6_1.3 U1_6_1.4 U1_6_1.5 U1_6_2.1 U1_6_2.2 U1_6_2.3 U1_6_2.4 U1_6_2.5 U1_7.1 U1_7.2 U1_7.3 U1_7.4 U1_7.5 U1_8.1 U1_8.2 U1_8.3 U1_8.4 U1_8.5 U2.1 U2.2 U2.3 U2_1.1 U2_1.2 U2_1.3 U2_2.1 U2_2.2 U2_2.3 U2_2_1.1 U2_2_1.2 U2_2_1.3 U2_2_2.1 U2_2_2.2 U2_2_2.3 U2_3.1 U2_3.2 U2_3.3 U2_3_1.1 U2_3_1.2 U2_3_1.3 U2_3_2.1 U2_3_2.2 U2_3_2.3 U2_4.1 U2_4.2 U2_4.3 U2_4_1.1 U2_4_1.2 U2_4_1.3 U2_4_2.1 U2_4_2.2 U2_4_2.3 U2_5.1 U2_5.2 U2_5.3 U2_5_1.1 U2_5_1.2 U2_5_1.3 U2_5_2.1 U2_5_2.2 U2_5_2.3 U2_6.1 U2_6.2 U2_6.3 U2_6_1.1 U2_6_1.2 U2_6_1.3 U2_6_2.1 U2_6_2.2 U2_6_2.3 U2_7.1 U2_7.2 U2_7.3 U2_8.1 U2_8.2 U2_8.3 U3.1 U3.2 U3.3 U3.4 U3.5 U3.6 U3_1.1 U3_1.2 U3_1.3 U3_1.4 U3_1.5 U3_1.6 U3_2.1 U3_2.2 U3_2.3 U3_2.4 U3_2.5 U3_2.6 U3_2_1.1 U3_2_1.2 U3_2_1.3 U3_2_1.4 U3_2_1.5 U3_2_1.6 U3_2_2.1 U3_2_2.2 U3_2_2.3 U3_2_2.4 U3_2_2.5 U3_2_2.6 U3_3.1 U3_3.2 U3_3.3 U3_3.4 U3_3.5 U3_3.6 U3_3_1.1 U3_3_1.2 U3_3_1.3 U3_3_1.4 U3_3_1.5 U3_3_1.6 U3_3_2.1 U3_3_2.2 U3_3_2.3 U3_3_2.4 U3_3_2.5 U3_3_2.6 U3_4.1 U3_4.2 U3_4.3 U3_4.4 U3_4.5 U3_4.6 U3_4_1.1 U3_4_1.2 U3_4_1.3 U3_4_1.4 U3_4_1.5 U3_4_1.6 U3_4_2.1 U3_4_2.2 U3_4_2.3 U3_4_2.4 U3_4_2.5 U3_4_2.6 U3_5.1 U3_5.2 U3_5.3 U3_5.4 U3_5.5 U3_5.6 U3_5_1.1 U3_5_1.2 U3_5_1.3 U3_5_1.4 U3_5_1.5 U3_5_1.6 U3_5_2.1 U3_5_2.2 U3_5_2.3 U3_5_2.4 U3_5_2.5 U3_5_2.6 U3_6.1 U3_6.2 U3_6.3 U3_6.4 U3_6.5 U3_6.6 U3_6_1.1 U3_6_1.2 U3_6_1.3 U3_6_1.4 U3_6_1.5 U3_6_1.6 U3_6_2.1 U3_6_2.2 U3_6_2.3 U3_6_2.4 U3_6_2.5 U3_6_2.6 U3_7.1 U3_7.2 U3_7.3 U3_7.4 U3_7.5 U3_7.6 U3_8.1 U3_8.2 U3_8.3 U3_8.4 U3_8.5 U3_8.6 U4.1 U4.2 U4.3 U4.4 U4.5 U4.6 U4.7 U4.8 U4.9 U4.10 U4.11 U4.12 U4.13 U4.14 U4.15 U4.16 U4.17 U4.18 U4.19 U4.20 U4_1.1 U4_1.2 U4_1.3 U4_1.4 U4_1.5 U4_1.6 U4_1.7 U4_1.8 U4_1.9 U4_1.10 U4_1.11 U4_1.12 U4_1.13 U4_1.14 U4_1.15 U4_1.16 U4_1.17 U4_1.18 U4_1.19 U4_1.20 U4_2.1 U4_2.2 U4_2.3 U4_2.4 U4_2.5 U4_2.6 U4_2.7 U4_2.8 U4_2.9 U4_2.10 U4_2.11 U4_2.12 U4_2.13 U4_2.14 U4_2.15 U4_2.16 U4_2.17 U4_2.18 U4_2.19 U4_2.20 U4_2_1.1 U4_2_1.2 U4_2_1.3 U4_2_1.4 U4_2_1.5 U4_2_1.6 U4_2_1.7 U4_2_1.8 U4_2_1.9 U4_2_1.10 U4_2_1.11 U4_2_1.12 U4_2_1.13 U4_2_1.14 U4_2_1.15 U4_2_1.16 U4_2_1.17 U4_2_1.18 U4_2_1.19 U4_2_1.20 U4_2_2.1 U4_2_2.2 U4_2_2.3 U4_2_2.4 U4_2_2.5 U4_2_2.6 U4_2_2.7 U4_2_2.8 U4_2_2.9 U4_2_2.10 U4_2_2.11 U4_2_2.12 U4_2_2.13 U4_2_2.14 U4_2_2.15 U4_2_2.16 U4_2_2.17 U4_2_2.18 U4_2_2.19 U4_2_2.20 U4_3.1 U4_3.2 U4_3.3 U4_3.4 U4_3.5 U4_3.6 U4_3.7 U4_3.8 U4_3.9 U4_3.10 U4_3.11 U4_3.12 U4_3.13 U4_3.14 U4_3.15 U4_3.16 U4_3.17 U4_3.18 U4_3.19 U4_3.20 U4_3_1.1 U4_3_1.2 U4_3_1.3 U4_3_1.4 U4_3_1.5 U4_3_1.6 U4_3_1.7 U4_3_1.8 U4_3_1.9 U4_3_1.10 U4_3_1.11 U4_3_1.12 U4_3_1.13 U4_3_1.14 U4_3_1.15 U4_3_1.16 U4_3_1.17 U4_3_1.18 U4_3_1.19 U4_3_1.20 U4_3_2.1 U4_3_2.2 U4_3_2.3 U4_3_2.4 U4_3_2.5 U4_3_2.6 U4_3_2.7 U4_3_2.8 U4_3_2.9 U4_3_2.10 U4_3_2.11 U4_3_2.12 U4_3_2.13 U4_3_2.14 U4_3_2.15 U4_3_2.16 U4_3_2.17 U4_3_2.18 U4_3_2.19 U4_3_2.20 U4_4.1 U4_4.2 U4_4.3 U4_4.4 U4_4.5 U4_4.6 U4_4.7 U4_4.8 U4_4.9 U4_4.10 U4_4.11 U4_4.12 U4_4.13 U4_4.14 U4_4.15 U4_4.16 U4_4.17 U4_4.18 U4_4.19 U4_4.20 U4_4_1.1 U4_4_1.2 U4_4_1.3 U4_4_1.4 U4_4_1.5 U4_4_1.6 U4_4_1.7 U4_4_1.8 U4_4_1.9 U4_4_1.10 U4_4_1.11 U4_4_1.12 U4_4_1.13 U4_4_1.14 U4_4_1.15 U4_4_1.16 U4_4_1.17 U4_4_1.18 U4_4_1.19 U4_4_1.20 U4_4_2.1 U4_4_2.2 U4_4_2.3 U4_4_2.4 U4_4_2.5 U4_4_2.6 U4_4_2.7 U4_4_2.8 U4_4_2.9 U4_4_2.10 U4_4_2.11 U4_4_2.12 U4_4_2.13 U4_4_2.14 U4_4_2.15 U4_4_2.16 U4_4_2.17 U4_4_2.18 U4_4_2.19 U4_4_2.20 U4_5.1 U4_5.2 U4_5.3 U4_5.4 U4_5.5 U4_5.6 U4_5.7 U4_5.8 U4_5.9 U4_5.10 U4_5.11 U4_5.12 U4_5.13 U4_5.14 U4_5.15 U4_5.16 U4_5.17 U4_5.18 U4_5.19 U4_5.20 U4_5_1.1 U4_5_1.2 U4_5_1.3 U4_5_1.4 U4_5_1.5 U4_5_1.6 U4_5_1.7 U4_5_1.8 U4_5_1.9 U4_5_1.10 U4_5_1.11 U4_5_1.12 U4_5_1.13 U4_5_1.14 U4_5_1.15 U4_5_1.16 U4_5_1.17 U4_5_1.18 U4_5_1.19 U4_5_1.20 U4_5_2.1 U4_5_2.2 U4_5_2.3 U4_5_2.4 U4_5_2.5 U4_5_2.6 U4_5_2.7 U4_5_2.8 U4_5_2.9 U4_5_2.10 U4_5_2.11 U4_5_2.12 U4_5_2.13 U4_5_2.14 U4_5_2.15 U4_5_2.16 U4_5_2.17 U4_5_2.18 U4_5_2.19 U4_5_2.20 U4_6.1 U4_6.2 U4_6.3 U4_6.4 U4_6.5 U4_6.6 U4_6.7 U4_6.8 U4_6.9 U4_6.10 U4_6.11 U4_6.12 U4_6.13 U4_6.14 U4_6.15 U4_6.16 U4_6.17 U4_6.18 U4_6.19 U4_6.20 U4_6_1.1 U4_6_1.2 U4_6_1.3 U4_6_1.4 U4_6_1.5 U4_6_1.6 U4_6_1.7 U4_6_1.8 U4_6_1.9 U4_6_1.10 U4_6_1.11 U4_6_1.12 U4_6_1.13 U4_6_1.14 U4_6_1.15 U4_6_1.16 U4_6_1.17 U4_6_1.18 U4_6_1.19 U4_6_1.20 U4_6_2.1 U4_6_2.2 U4_6_2.3 U4_6_2.4 U4_6_2.5 U4_6_2.6 U4_6_2.7 U4_6_2.8 U4_6_2.9 U4_6_2.10 U4_6_2.11 U4_6_2.12 U4_6_2.13 U4_6_2.14 U4_6_2.15 U4_6_2.16 U4_6_2.17 U4_6_2.18 U4_6_2.19 U4_6_2.20 U4_7.1 U4_7.2 U4_7.3 U4_7.4 U4_7.5 U4_7.6 U4_7.7 U4_7.8 U4_7.9 U4_7.10 U4_7.11 U4_7.12 U4_7.13 U4_7.14 U4_7.15 U4_7.16 U4_7.17 U4_7.18 U4_7.19 U4_7.20 U4_8.1 U4_8.2 U4_8.3 U4_8.4 U4_8.5 U4_8.6 U4_8.7 U4_8.8 U4_8.9 U4_8.10 U4_8.11 U4_8.12 U4_8.13 U4_8.14 U4_8.15 U4_8.16 U4_8.17 U4_8.18 U4_8.19 U4_8.20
